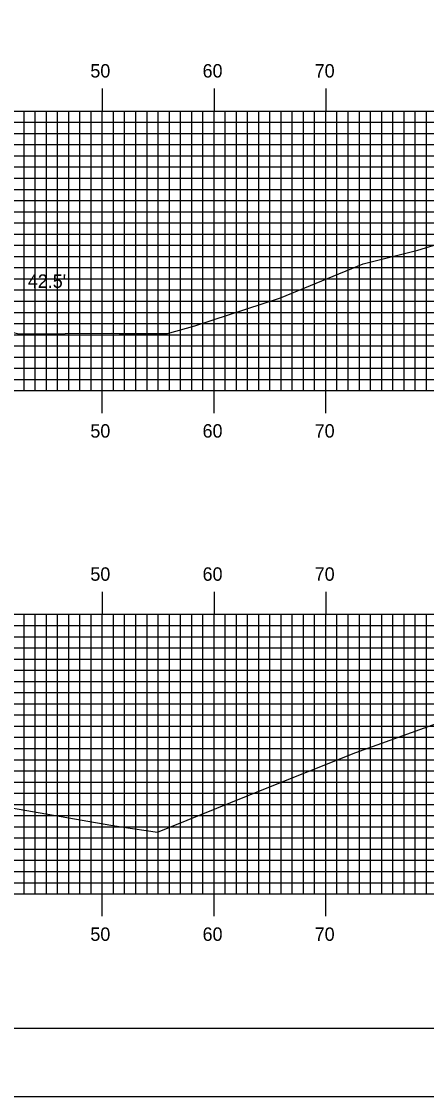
# Model space of a CAD drawing. Extents: x 843356 to 843699, y 363538 to 363758.
# Drawn here: x 843564.2 to 843600.4, y 363537.6 to 363633.7 of the extents above; entities that cross this region are included whole.
import ezdxf

# ---------------------------------------------------------------- set-up
doc = ezdxf.new("R2010")
doc.units = 0
for name, color, linetype in [('BORDER', 7, 'Continuous'), ('D_Text_Standard', 7, 'Continuous'), ('H_V ANNOTATION', 7, 'Continuous'), ('MAJOR', 7, 'Continuous'), ('MINOR', 7, 'Continuous'), ('PLOT BOUNDARY', 7, 'Continuous'), ('S_Roadway_Centerline', 7, 'Continuous')]:
    doc.layers.add(name, color=color, linetype=linetype)

msp = doc.modelspace()

# ---------------------------------------------------------------- linework, layer by layer
at = {"layer": 'BORDER'}
msp.add_lwpolyline([(843371.824, 363543.721), (843691.824, 363543.721), (843691.824, 363753.721), (843371.824, 363753.721)], close=True, dxfattribs=at)
at = {"layer": 'MAJOR'}
for p, q in [((843571.424, 363627.725), (843571.424, 363625.721)), ((843581.424, 363627.725), (843581.424, 363625.721)), ((843591.424, 363627.725), (843591.424, 363625.721)), ((843381.424, 363625.721), (843661.424, 363625.721)), ((843381.424, 363625.721), (843661.424, 363625.721)), ((843571.424, 363600.721), (843571.424, 363625.721)), ((843581.424, 363600.721), (843581.424, 363625.721)), ((843591.424, 363600.721), (843591.424, 363625.721)), ((843381.424, 363620.721), (843661.424, 363620.721)), ((843381.424, 363615.721), (843661.424, 363615.721)), ((843381.424, 363610.721), (843661.424, 363610.721)), ((843381.424, 363605.721), (843661.424, 363605.721)), ((843381.424, 363600.721), (843661.424, 363600.721)), ((843381.424, 363600.721), (843661.424, 363600.721)), ((843571.424, 363598.717), (843571.424, 363600.721)), ((843581.424, 363598.717), (843581.424, 363600.721)), ((843591.424, 363598.717), (843591.424, 363600.721)), ((843571.424, 363582.725), (843571.424, 363580.721)), ((843581.424, 363582.725), (843581.424, 363580.721)), ((843591.424, 363582.725), (843591.424, 363580.721)), ((843381.424, 363580.721), (843661.424, 363580.721)), ((843381.424, 363580.721), (843661.424, 363580.721)), ((843571.424, 363555.721), (843571.424, 363580.721)), ((843581.424, 363555.721), (843581.424, 363580.721)), ((843591.424, 363555.721), (843591.424, 363580.721)), ((843381.424, 363575.721), (843661.424, 363575.721)), ((843381.424, 363570.721), (843661.424, 363570.721)), ((843381.424, 363565.721), (843661.424, 363565.721)), ((843381.424, 363560.721), (843661.424, 363560.721)), ((843381.424, 363555.721), (843661.424, 363555.721)), ((843381.424, 363555.721), (843661.424, 363555.721)), ((843571.424, 363553.717), (843571.424, 363555.721)), ((843581.424, 363553.717), (843581.424, 363555.721)), ((843591.424, 363553.717), (843591.424, 363555.721))]:
    msp.add_line(p, q, dxfattribs=at)
at = {"layer": 'MINOR'}
for p, q in [((843564.424, 363600.721), (843564.424, 363625.721)), ((843565.424, 363600.721), (843565.424, 363625.721)), ((843566.424, 363600.721), (843566.424, 363625.721)), ((843567.424, 363600.721), (843567.424, 363625.721)), ((843568.424, 363600.721), (843568.424, 363625.721)), ((843569.424, 363600.721), (843569.424, 363625.721)), ((843570.424, 363600.721), (843570.424, 363625.721)), ((843572.424, 363600.721), (843572.424, 363625.721)), ((843573.424, 363600.721), (843573.424, 363625.721)), ((843574.424, 363600.721), (843574.424, 363625.721)), ((843575.424, 363600.721), (843575.424, 363625.721)), ((843576.424, 363600.721), (843576.424, 363625.721)), ((843577.424, 363600.721), (843577.424, 363625.721)), ((843578.424, 363600.721), (843578.424, 363625.721)), ((843579.424, 363600.721), (843579.424, 363625.721)), ((843580.424, 363600.721), (843580.424, 363625.721)), ((843582.424, 363600.721), (843582.424, 363625.721)), ((843583.424, 363600.721), (843583.424, 363625.721)), ((843584.424, 363600.721), (843584.424, 363625.721)), ((843585.424, 363600.721), (843585.424, 363625.721)), ((843586.424, 363600.721), (843586.424, 363625.721)), ((843587.424, 363600.721), (843587.424, 363625.721)), ((843588.424, 363600.721), (843588.424, 363625.721)), ((843589.424, 363600.721), (843589.424, 363625.721)), ((843590.424, 363600.721), (843590.424, 363625.721)), ((843592.424, 363600.721), (843592.424, 363625.721)), ((843593.424, 363600.721), (843593.424, 363625.721)), ((843594.424, 363600.721), (843594.424, 363625.721)), ((843595.424, 363600.721), (843595.424, 363625.721)), ((843596.424, 363600.721), (843596.424, 363625.721)), ((843597.424, 363600.721), (843597.424, 363625.721)), ((843598.424, 363600.721), (843598.424, 363625.721)), ((843599.424, 363600.721), (843599.424, 363625.721)), ((843600.424, 363600.721), (843600.424, 363625.721)), ((843381.424, 363624.721), (843661.424, 363624.721)), ((843381.424, 363623.721), (843661.424, 363623.721)), ((843381.424, 363622.721), (843661.424, 363622.721)), ((843381.424, 363621.721), (843661.424, 363621.721)), ((843381.424, 363619.721), (843661.424, 363619.721)), ((843381.424, 363618.721), (843661.424, 363618.721)), ((843381.424, 363617.721), (843661.424, 363617.721)), ((843381.424, 363616.721), (843661.424, 363616.721)), ((843381.424, 363614.721), (843661.424, 363614.721)), ((843381.424, 363613.721), (843661.424, 363613.721)), ((843381.424, 363612.721), (843661.424, 363612.721)), ((843381.424, 363611.721), (843661.424, 363611.721)), ((843381.424, 363609.721), (843661.424, 363609.721)), ((843381.424, 363608.721), (843661.424, 363608.721)), ((843381.424, 363607.721), (843661.424, 363607.721)), ((843381.424, 363606.721), (843661.424, 363606.721)), ((843381.424, 363604.721), (843661.424, 363604.721)), ((843381.424, 363603.721), (843661.424, 363603.721)), ((843381.424, 363602.721), (843661.424, 363602.721)), ((843381.424, 363601.721), (843661.424, 363601.721)), ((843564.424, 363555.721), (843564.424, 363580.721)), ((843565.424, 363555.721), (843565.424, 363580.721)), ((843566.424, 363555.721), (843566.424, 363580.721)), ((843567.424, 363555.721), (843567.424, 363580.721)), ((843568.424, 363555.721), (843568.424, 363580.721)), ((843569.424, 363555.721), (843569.424, 363580.721)), ((843570.424, 363555.721), (843570.424, 363580.721)), ((843572.424, 363555.721), (843572.424, 363580.721)), ((843573.424, 363555.721), (843573.424, 363580.721)), ((843574.424, 363555.721), (843574.424, 363580.721)), ((843575.424, 363555.721), (843575.424, 363580.721)), ((843576.424, 363555.721), (843576.424, 363580.721)), ((843577.424, 363555.721), (843577.424, 363580.721)), ((843578.424, 363555.721), (843578.424, 363580.721)), ((843579.424, 363555.721), (843579.424, 363580.721)), ((843580.424, 363555.721), (843580.424, 363580.721)), ((843582.424, 363555.721), (843582.424, 363580.721)), ((843583.424, 363555.721), (843583.424, 363580.721)), ((843584.424, 363555.721), (843584.424, 363580.721)), ((843585.424, 363555.721), (843585.424, 363580.721)), ((843586.424, 363555.721), (843586.424, 363580.721)), ((843587.424, 363555.721), (843587.424, 363580.721)), ((843588.424, 363555.721), (843588.424, 363580.721)), ((843589.424, 363555.721), (843589.424, 363580.721)), ((843590.424, 363555.721), (843590.424, 363580.721)), ((843592.424, 363555.721), (843592.424, 363580.721)), ((843593.424, 363555.721), (843593.424, 363580.721)), ((843594.424, 363555.721), (843594.424, 363580.721)), ((843595.424, 363555.721), (843595.424, 363580.721)), ((843596.424, 363555.721), (843596.424, 363580.721)), ((843597.424, 363555.721), (843597.424, 363580.721)), ((843598.424, 363555.721), (843598.424, 363580.721)), ((843599.424, 363555.721), (843599.424, 363580.721)), ((843600.424, 363555.721), (843600.424, 363580.721)), ((843381.424, 363579.721), (843661.424, 363579.721)), ((843381.424, 363578.721), (843661.424, 363578.721)), ((843381.424, 363577.721), (843661.424, 363577.721)), ((843381.424, 363576.721), (843661.424, 363576.721)), ((843381.424, 363574.721), (843661.424, 363574.721)), ((843381.424, 363573.721), (843661.424, 363573.721)), ((843381.424, 363572.721), (843661.424, 363572.721)), ((843381.424, 363571.721), (843661.424, 363571.721)), ((843381.424, 363569.721), (843661.424, 363569.721)), ((843381.424, 363568.721), (843661.424, 363568.721)), ((843381.424, 363567.721), (843661.424, 363567.721)), ((843381.424, 363566.721), (843661.424, 363566.721)), ((843381.424, 363564.721), (843661.424, 363564.721)), ((843381.424, 363563.721), (843661.424, 363563.721)), ((843381.424, 363562.721), (843661.424, 363562.721)), ((843381.424, 363561.721), (843661.424, 363561.721)), ((843381.424, 363559.721), (843661.424, 363559.721)), ((843381.424, 363558.721), (843661.424, 363558.721)), ((843381.424, 363557.721), (843661.424, 363557.721)), ((843381.424, 363556.721), (843661.424, 363556.721))]:
    msp.add_line(p, q, dxfattribs=at)
at = {"layer": 'PLOT BOUNDARY'}
msp.add_lwpolyline([(843355.638, 363537.603), (843695.638, 363537.603), (843695.638, 363757.603), (843355.638, 363757.603)], close=True, dxfattribs=at)
at = {"layer": 'S_Roadway_Centerline'}
for points in [[(843500.734, 363614.006), (843508.07, 363614.076), (843508.892, 363614.076), (843511.252, 363614.056), (843523.119, 363613.849), (843524.157, 363613.834), (843526.837, 363613.71), (843534.194, 363613.277), (843535.257, 363613.198), (843539.3, 363612.586), (843543.743, 363612.01), (843549.991, 363611.121), (843560.013, 363606.776), (843562.204, 363606.204), (843563.96, 363605.815), (843572.238, 363605.857), (843572.92, 363605.839), (843577.258, 363605.822), (843579.697, 363606.524), (843587.369, 363609.026), (843594.753, 363612.067), (843599.661, 363613.294), (843607.961, 363615.829)], [(843500.121, 363569.26), (843507.382, 363569.351), (843510.071, 363569.407), (843512.294, 363569.376), (843513.155, 363569.367), (843521.066, 363569.12), (843532.991, 363568.776), (843534.059, 363568.732), (843534.639, 363568.656), (843538.204, 363568.023), (843542.218, 363567.397), (843548.874, 363566.238), (843552.851, 363565.447), (843560.709, 363563.854), (843572.188, 363561.879), (843573.125, 363561.724), (843576.365, 363561.239), (843585.567, 363564.955), (843594.124, 363568.35), (843602.151, 363571.244)]]:
    msp.add_lwpolyline(points, dxfattribs=at)

# ---------------------------------------------------------------- texts
at = {"layer": 'D_Text_Standard'}
msp.add_text("42.5'", height=1.2, dxfattribs=at).set_placement((843564.757, 363609.913))
at = {"layer": 'H_V ANNOTATION'}
for s, p in [('50', (843570.354, 363628.721)), ('60', (843580.397, 363628.721)), ('70', (843590.428, 363628.721)), ('50', (843570.354, 363596.521)), ('60', (843580.397, 363596.521)), ('70', (843590.428, 363596.521)), ('50', (843570.354, 363583.721)), ('60', (843580.397, 363583.721)), ('70', (843590.428, 363583.721)), ('50', (843570.354, 363551.521)), ('60', (843580.397, 363551.521)), ('70', (843590.428, 363551.521))]:
    msp.add_text(s, height=1.2, dxfattribs=at).set_placement(p)

doc.saveas('drawing.dxf')
